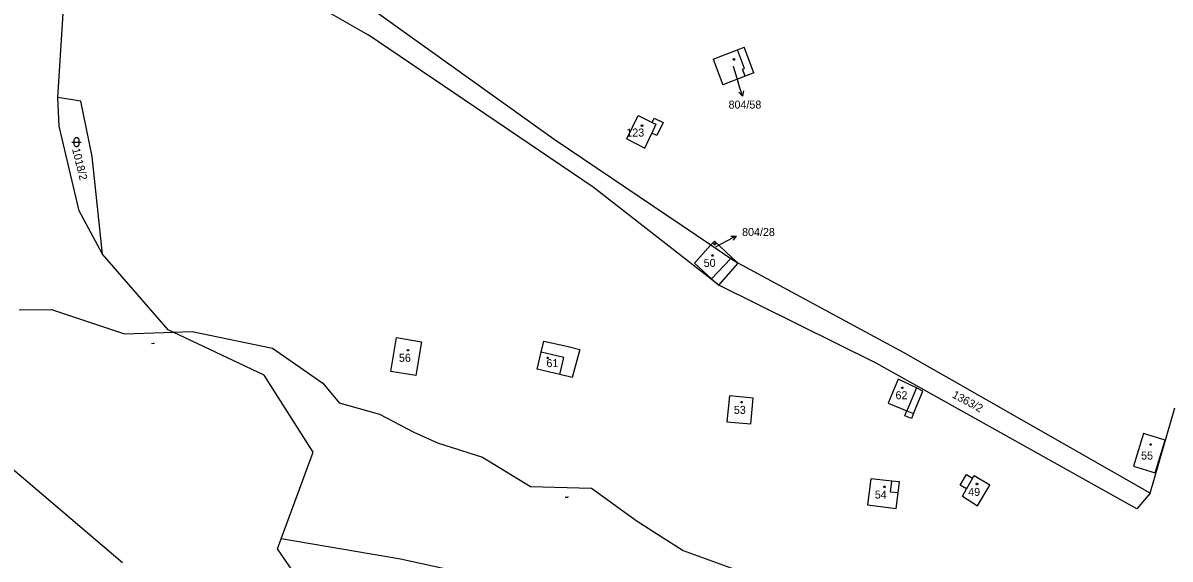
# Model space of a CAD drawing. Extents: x -845995 to -842497, y -1063614 to -1059680.
# Drawn here: x -843977.7 to -843734.2, y -1061643.6 to -1061529.9 of the extents above; entities that cross this region are included whole.
import ezdxf

# ---------------------------------------------------------------- set-up
doc = ezdxf.new("R2010")
doc.units = 0
for name, color, linetype in [('KN_HRANICE', 7, 'Continuous'), ('KN_KULTURY', 7, 'Continuous'), ('KN_PARCELY', 7, 'Continuous'), ('KN_SLUCKY', 7, 'Continuous'), ('KN_STAVEBNI', 7, 'Continuous')]:
    doc.layers.add(name, color=color, linetype=linetype)

# ---------------------------------------------------------------- blocks, each defined once
blk = doc.blocks.new('316')
for points in [[(-1, 1), (0.27, 1), (1, 1)], [(-0.5, 1.5), (-0.4, 1.79), (-0.15, 1.97), (0.16, 1.97), (0.41, 1.79), (0.51, 1.5), (0.51, 0.5), (0.41, 0.21), (0.16, 0.03), (-0.15, 0.03), (-0.4, 0.21), (-0.5, 0.5), (-0.5, 1.5)]]:
    blk.add_lwpolyline(points)
blk = doc.blocks.new('10292')
blk.add_line((0, 3), (0, 0))
blk.add_lwpolyline([(-0.5, 2), (0, 3), (0.5, 2)])
blk = doc.blocks.new('1060')
blk.add_line((-0.3, 0), (0.3, 0))
blk.add_lwpolyline([(0.18, 0.04), (0.3, 0), (0.18, -0.04)])
blk = doc.blocks.new('402')
blk.add_lwpolyline([(0.09, 0.15), (0.18, 0), (0.09, -0.15), (-0.09, -0.15), (-0.18, 0), (-0.09, 0.15), (0.09, 0.15)])

msp = doc.modelspace()

# ---------------------------------------------------------------- linework, layer by layer
at = {"layer": 'KN_HRANICE'}
for p, q in [((-843970.29, -1061545.7), (-843968.17, -1061511.54)), ((-843922.86, -1061521.79), (-843904.45, -1061532.36)), ((-843903.73, -1061526.81), (-843864.94, -1061554.51)), ((-843856.65, -1061564.71), (-843904.45, -1061532.36)), ((-843831.18, -1061537.5), (-843825.99, -1061535.55)), ((-843825.99, -1061535.55), (-843824.56, -1061535.01)), ((-843822.53, -1061540.42), (-843824.56, -1061535.01)), ((-843831.18, -1061537.5), (-843829.14, -1061542.95)), ((-843824.38, -1061541.13), (-843829.14, -1061542.95)), ((-843822.53, -1061540.42), (-843824.38, -1061541.13)), ((-843970, -1061551.72), (-843970.29, -1061545.7)), ((-843965.46, -1061546.41), (-843970.29, -1061545.7)), ((-843963.03, -1061558.2), (-843965.46, -1061546.41)), ((-843849.53, -1061554.46), (-843847.07, -1061549.5)), ((-843847.07, -1061549.5), (-843844.11, -1061550.94)), ((-843844.11, -1061550.94), (-843843.67, -1061550.02)), ((-843843.67, -1061550.02), (-843841.76, -1061550.95)), ((-843841.76, -1061550.95), (-843843.12, -1061553.75)), ((-843965.78, -1061569.71), (-843970, -1061551.72)), ((-843845.71, -1061556.41), (-843844.2, -1061553.23)), ((-843843.12, -1061553.75), (-843844.2, -1061553.23)), ((-843864.94, -1061554.51), (-843831.65, -1061576.95)), ((-843849.53, -1061554.46), (-843845.71, -1061556.41)), ((-843960.81, -1061578.91), (-843963.03, -1061558.2)), ((-843829.99, -1061585.51), (-843856.65, -1061564.71)), ((-843960.81, -1061578.91), (-843965.78, -1061569.71)), ((-843831.65, -1061576.95), (-843835.12, -1061580.8)), ((-843830.92, -1061576.15), (-843831.65, -1061576.95)), ((-843831.65, -1061576.95), (-843827.4, -1061579.81)), ((-843827.21, -1061579.61), (-843830.92, -1061576.15)), ((-843946.88, -1061594.96), (-843960.81, -1061578.91)), ((-843835.12, -1061580.8), (-843831.52, -1061584.12)), ((-843829.99, -1061585.51), (-843825.88, -1061580.84)), ((-843827.4, -1061579.81), (-843825.88, -1061580.84)), ((-843825.88, -1061580.84), (-843827.21, -1061579.61)), ((-843790.75, -1061599.79), (-843825.88, -1061580.84)), ((-843831.52, -1061584.12), (-843829.99, -1061585.51)), ((-843796.57, -1061602.04), (-843829.99, -1061585.51)), ((-843945.8, -1061595.47), (-843946.88, -1061594.96)), ((-843926.49, -1061604.54), (-843945.8, -1061595.47)), ((-843899.6, -1061603.78), (-843898.4, -1061596.6)), ((-843898.4, -1061596.6), (-843893.09, -1061597.49)), ((-843893.09, -1061597.49), (-843894.29, -1061604.67)), ((-843867.68, -1061599.68), (-843867.14, -1061597.35)), ((-843867.14, -1061597.35), (-843862.26, -1061598.45)), ((-843868.53, -1061603.3), (-843867.68, -1061599.68)), ((-843862.26, -1061598.45), (-843859.49, -1061599.15)), ((-843859.49, -1061599.15), (-843861.14, -1061605.09)), ((-843738.36, -1061629.63), (-843790.75, -1061599.79)), ((-843741.22, -1061632.91), (-843796.57, -1061602.04)), ((-843916.09, -1061620.9), (-843926.49, -1061604.54)), ((-843894.29, -1061604.67), (-843899.6, -1061603.78)), ((-843863.73, -1061604.46), (-843868.53, -1061603.3)), ((-843861.14, -1061605.09), (-843863.73, -1061604.46)), ((-843791.86, -1061605.4), (-843794.02, -1061610.48)), ((-843787.99, -1061607.29), (-843791.86, -1061605.4)), ((-843786.62, -1061607.96), (-843787.99, -1061607.29)), ((-843827.72, -1061608.98), (-843828.25, -1061614.46)), ((-843822.66, -1061609.42), (-843827.72, -1061608.98)), ((-843823.17, -1061614.92), (-843822.66, -1061609.42)), ((-843788.66, -1061612.73), (-843786.62, -1061607.96)), ((-843794.02, -1061610.48), (-843790.06, -1061612.14)), ((-843790.49, -1061613.17), (-843790.06, -1061612.14)), ((-843738.36, -1061629.63), (-843733.15, -1061611.51)), ((-843828.25, -1061614.46), (-843823.17, -1061614.92)), ((-843789.09, -1061613.75), (-843790.49, -1061613.17)), ((-843788.66, -1061612.73), (-843789.09, -1061613.75)), ((-843739.78, -1061616.97), (-843741.91, -1061623.89)), ((-843735.17, -1061618.38), (-843739.78, -1061616.97)), ((-843737.3, -1061625.27), (-843735.17, -1061618.38)), ((-843922.9, -1061639.31), (-843916.09, -1061620.9)), ((-843980.43, -1061623.99), (-843956.56, -1061644.28)), ((-843741.91, -1061623.89), (-843737.3, -1061625.27)), ((-843797.7, -1061626.55), (-843798.4, -1061632.11)), ((-843793.25, -1061627.06), (-843797.7, -1061626.55)), ((-843791.58, -1061627.21), (-843793.25, -1061627.06)), ((-843778.7, -1061627.88), (-843777.35, -1061625.62)), ((-843777.35, -1061625.62), (-843776.08, -1061626.44)), ((-843776.08, -1061626.44), (-843775.77, -1061625.89)), ((-843772.46, -1061627.93), (-843775.77, -1061625.89)), ((-843792.32, -1061632.83), (-843791.89, -1061629.54)), ((-843791.89, -1061629.54), (-843791.58, -1061627.21)), ((-843777.36, -1061628.7), (-843778.7, -1061627.88)), ((-843778.23, -1061630.23), (-843777.36, -1061628.7)), ((-843775.02, -1061632.26), (-843772.46, -1061627.93)), ((-843778.23, -1061630.23), (-843775.02, -1061632.26)), ((-843738.36, -1061629.63), (-843741.22, -1061632.91)), ((-843798.4, -1061632.11), (-843792.32, -1061632.83)), ((-843923.67, -1061641.39), (-843922.9, -1061639.31)), ((-843897.56, -1061643.57), (-843922.9, -1061639.31)), ((-843906.26, -1061666.89), (-843923.67, -1061641.39)), ((-843875.53, -1061648.44), (-843897.56, -1061643.57))]:
    msp.add_line(p, q, dxfattribs=at)
at = {"layer": 'KN_PARCELY'}
for p, q in [((-843826.95, -1061539.02), (-843825.84, -1061542.5)), ((-843830.5, -1061577.28), (-843828.92, -1061576.45))]:
    msp.add_line(p, q, dxfattribs=at)
at = {"layer": 'KN_SLUCKY'}
for p, q in [((-843824.55, -1061539.49), (-843825.99, -1061535.55)), ((-843824.93, -1061539.63), (-843824.55, -1061539.49)), ((-843824.38, -1061541.13), (-843824.93, -1061539.63)), ((-843843.31, -1061551.33), (-843844.2, -1061553.23)), ((-843844.11, -1061550.94), (-843843.31, -1061551.33)), ((-843831.52, -1061584.12), (-843827.4, -1061579.81)), ((-843827.4, -1061579.81), (-843827.21, -1061579.61)), ((-843978.52, -1061590.71), (-843971.65, -1061590.62)), ((-843971.65, -1061590.62), (-843956.13, -1061595.8)), ((-843956.13, -1061595.8), (-843945.8, -1061595.47)), ((-843945.8, -1061595.47), (-843941.82, -1061595.34)), ((-843941.82, -1061595.34), (-843924.72, -1061598.84)), ((-843924.72, -1061598.84), (-843914.07, -1061606.3)), ((-843862.87, -1061600.83), (-843867.68, -1061599.68)), ((-843863.73, -1061604.46), (-843862.87, -1061600.83)), ((-843914.07, -1061606.3), (-843910.57, -1061610.41)), ((-843787.99, -1061607.29), (-843790.06, -1061612.14)), ((-843910.57, -1061610.41), (-843902.05, -1061612.84)), ((-843790.06, -1061612.14), (-843788.66, -1061612.73)), ((-843902.05, -1061612.84), (-843894.75, -1061616.65)), ((-843894.75, -1061616.65), (-843889.73, -1061618.93)), ((-843889.73, -1061618.93), (-843880.14, -1061621.98)), ((-843880.14, -1061621.98), (-843869.95, -1061628.22)), ((-843793.53, -1061629.37), (-843793.25, -1061627.06)), ((-843776.08, -1061626.44), (-843777.36, -1061628.7)), ((-843869.95, -1061628.22), (-843857.02, -1061628.52)), ((-843857.02, -1061628.52), (-843847.28, -1061635.52)), ((-843791.89, -1061629.54), (-843793.53, -1061629.37)), ((-843847.28, -1061635.52), (-843837.54, -1061641.77)), ((-843837.54, -1061641.77), (-843826.63, -1061645.7))]:
    msp.add_line(p, q, dxfattribs=at)
at = {"layer": 'KN_STAVEBNI'}
for p, q in [((-843831.18, -1061537.5), (-843825.99, -1061535.55)), ((-843824.55, -1061539.49), (-843825.99, -1061535.55)), ((-843831.18, -1061537.5), (-843829.14, -1061542.95)), ((-843824.93, -1061539.63), (-843824.55, -1061539.49)), ((-843824.38, -1061541.13), (-843829.14, -1061542.95)), ((-843824.38, -1061541.13), (-843824.93, -1061539.63)), ((-843849.53, -1061554.46), (-843847.07, -1061549.5)), ((-843847.07, -1061549.5), (-843844.11, -1061550.94)), ((-843843.31, -1061551.33), (-843844.2, -1061553.23)), ((-843844.11, -1061550.94), (-843843.31, -1061551.33)), ((-843845.71, -1061556.41), (-843844.2, -1061553.23)), ((-843849.53, -1061554.46), (-843845.71, -1061556.41)), ((-843831.65, -1061576.95), (-843835.12, -1061580.8)), ((-843830.92, -1061576.15), (-843831.65, -1061576.95)), ((-843827.21, -1061579.61), (-843830.92, -1061576.15)), ((-843835.12, -1061580.8), (-843831.52, -1061584.12)), ((-843831.52, -1061584.12), (-843827.4, -1061579.81)), ((-843827.4, -1061579.81), (-843827.21, -1061579.61)), ((-843899.6, -1061603.78), (-843898.4, -1061596.6)), ((-843898.4, -1061596.6), (-843893.09, -1061597.49)), ((-843893.09, -1061597.49), (-843894.29, -1061604.67)), ((-843868.53, -1061603.3), (-843867.68, -1061599.68)), ((-843862.87, -1061600.83), (-843867.68, -1061599.68)), ((-843863.73, -1061604.46), (-843862.87, -1061600.83)), ((-843894.29, -1061604.67), (-843899.6, -1061603.78)), ((-843863.73, -1061604.46), (-843868.53, -1061603.3)), ((-843791.86, -1061605.4), (-843794.02, -1061610.48)), ((-843787.99, -1061607.29), (-843791.86, -1061605.4)), ((-843787.99, -1061607.29), (-843790.06, -1061612.14)), ((-843827.72, -1061608.98), (-843828.25, -1061614.46)), ((-843822.66, -1061609.42), (-843827.72, -1061608.98)), ((-843823.17, -1061614.92), (-843822.66, -1061609.42)), ((-843794.02, -1061610.48), (-843790.06, -1061612.14)), ((-843828.25, -1061614.46), (-843823.17, -1061614.92)), ((-843739.78, -1061616.97), (-843741.91, -1061623.89)), ((-843735.17, -1061618.38), (-843739.78, -1061616.97)), ((-843737.3, -1061625.27), (-843735.17, -1061618.38)), ((-843741.91, -1061623.89), (-843737.3, -1061625.27)), ((-843797.7, -1061626.55), (-843798.4, -1061632.11)), ((-843793.25, -1061627.06), (-843797.7, -1061626.55)), ((-843793.53, -1061629.37), (-843793.25, -1061627.06)), ((-843776.08, -1061626.44), (-843777.36, -1061628.7)), ((-843776.08, -1061626.44), (-843775.77, -1061625.89)), ((-843772.46, -1061627.93), (-843775.77, -1061625.89)), ((-843791.89, -1061629.54), (-843793.53, -1061629.37)), ((-843792.32, -1061632.83), (-843791.89, -1061629.54)), ((-843778.23, -1061630.23), (-843777.36, -1061628.7)), ((-843775.02, -1061632.26), (-843772.46, -1061627.93)), ((-843778.23, -1061630.23), (-843775.02, -1061632.26)), ((-843798.4, -1061632.11), (-843792.32, -1061632.83))]:
    msp.add_line(p, q, dxfattribs=at)

# ---------------------------------------------------------------- block references
at = {"layer": 'KN_KULTURY'}
for name, p in [('402', (-843826.77, -1061537.57)), ('402', (-843846.29, -1061551.64)), ('316', (-843966.34, -1061556.13)), ('402', (-843830.87, -1061576.75)), ('402', (-843831.31, -1061579.17)), ('402', (-843895.97, -1061599.24)), ('402', (-843866.29, -1061600.9)), ('402', (-843791, -1061607.27)), ('402', (-843825.14, -1061610.29)), ('402', (-843738.3, -1061619.29)), ('402', (-843794.79, -1061628.25)), ('402', (-843775.17, -1061627.65))]:
    msp.add_blockref(name, p, dxfattribs=at)
at = {"layer": 'KN_PARCELY'}
for name, p, rotation in [('10292', (-843825.84, -1061542.5), -162.329561), ('10292', (-843828.92, -1061576.45), -62.176538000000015), ('1060', (-843950.15, -1061597.81), 1.7188729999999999)]:
    msp.add_blockref(name, p, dxfattribs=dict(at, rotation=rotation))
msp.add_blockref('1060', (-843862.29, -1061630.43), dxfattribs=at)

# ---------------------------------------------------------------- texts
for s, height, p in [('804/58', 0.1, (-843827.24, -1061539.02)), ('804/58', 1.7, (-843827.9, -1061548.02)), ('123', 1.7, (-843849.61, -1061553.95)), ('804/28', 1.7, (-843825.03, -1061575.05)), ('804/28', 0.1, (-843830.79, -1061577.28)), ('50', 1.7, (-843833.18, -1061581.6)), ('56', 1.7, (-843897.89, -1061601.74)), ('61', 1.7, (-843866.57, -1061602.87)), ('62', 1.7, (-843792.45, -1061609.68)), ('53', 1.7, (-843826.78, -1061612.78)), ('55', 1.7, (-843740.31, -1061622.47)), ('54', 1.7, (-843796.85, -1061630.74)), ('49', 1.7, (-843777.02, -1061630.18))]:
    msp.add_text(s, height=height, dxfattribs=at).set_placement(p)
for s, rotation, p in [('1018/2', 284.13, (-843967.32, -1061556.62)), ('1363/2', 331.628, (-843780.58, -1061609.22))]:
    msp.add_text(s, height=1.7, rotation=rotation, dxfattribs=at).set_placement(p)

doc.saveas('drawing.dxf')
